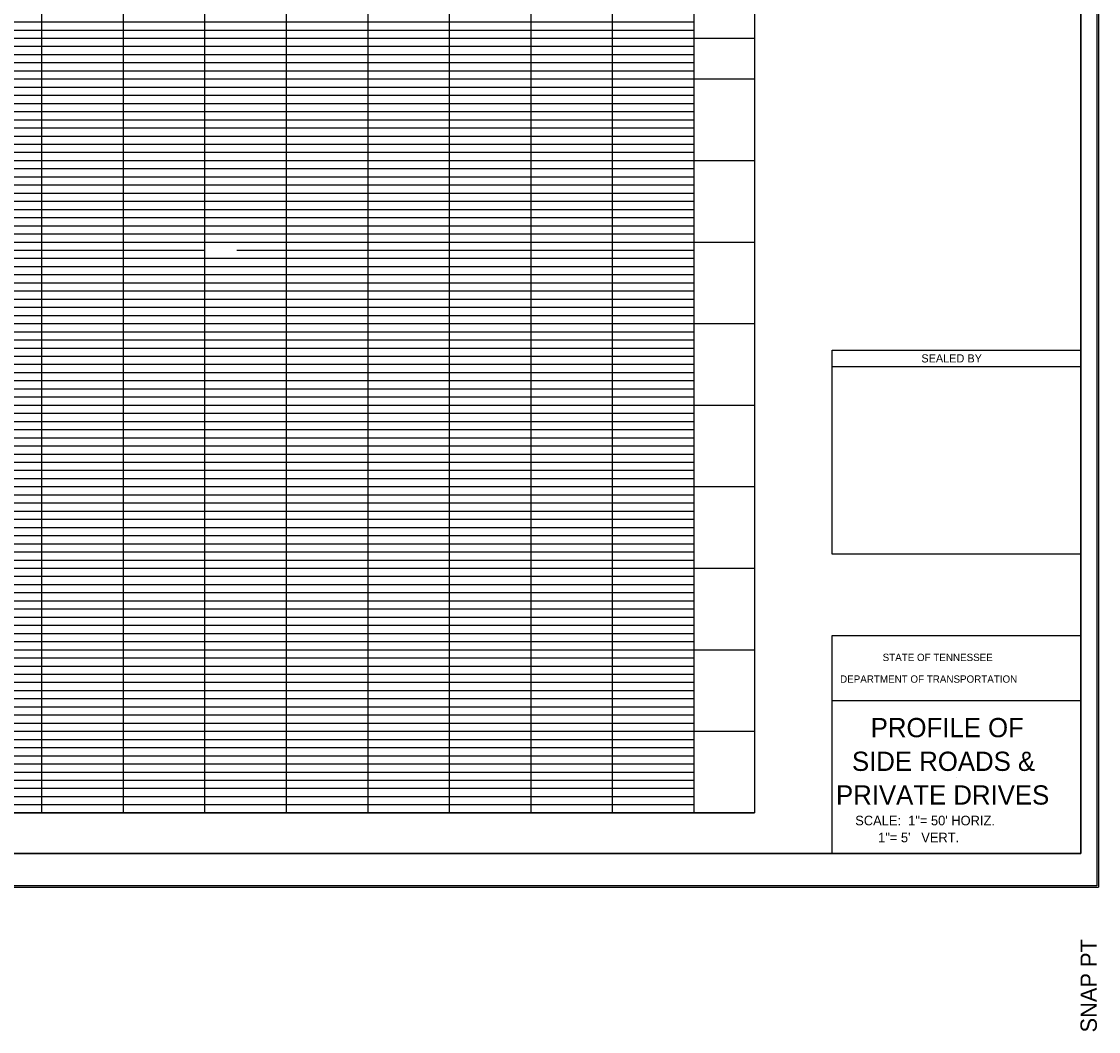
# Model space of a CAD drawing. Extents: x -200 to 1681865, y -325 to 520634.
# Drawn here: x 1681205 to 1681865, y 519391 to 520010 of the extents above; entities that cross this region are included whole.
import ezdxf

# ---------------------------------------------------------------- set-up
doc = ezdxf.new("R2010")
doc.units = 0
for name, color, linetype in [('DESIGN - SCRATCH - User 1', 7, 'Continuous'), ('DESIGN - SHEET - Corner Text', 7, 'Continuous'), ('DESIGN - SHEET - Light Grid', 7, 'Continuous'), ('DESIGN - SHEET - Linework', 7, 'Continuous'), ('DESIGN - SHEET - Plot Shape', 7, 'Continuous')]:
    doc.layers.add(name, color=color, linetype=linetype)

msp = doc.modelspace()

# ---------------------------------------------------------------- linework, layer by layer
at = {"layer": 'DESIGN - SCRATCH - User 1'}
msp.add_line((1681777.98, 519546.56), (1681777.98, 519546.56), dxfattribs=at)
at = {"layer": 'DESIGN - SHEET - Corner Text'}
msp.add_line((1680280.03, 519999.76), (1681654.23, 519999.76), dxfattribs=at)
at = {"layer": 'DESIGN - SHEET - Light Grid'}
for p, q in [((1680967.13, 520009.76), (1681317.13, 520009.76)), ((1681317.13, 520009.76), (1681617.13, 520009.76)), ((1680967.13, 520004.76), (1681317.13, 520004.76)), ((1680967.13, 519999.76), (1681317.13, 519999.76)), ((1681317.13, 520004.76), (1681617.13, 520004.76)), ((1681317.13, 519999.76), (1681617.13, 519999.76)), ((1680967.13, 519994.76), (1681317.13, 519994.76)), ((1681317.13, 519994.76), (1681617.13, 519994.76)), ((1680967.13, 519989.76), (1681317.13, 519989.76)), ((1681317.13, 519989.76), (1681617.13, 519989.76)), ((1680967.13, 519984.76), (1681317.13, 519984.76)), ((1680967.13, 519979.76), (1681317.13, 519979.76)), ((1681317.13, 519984.76), (1681617.13, 519984.76)), ((1681317.13, 519979.76), (1681617.13, 519979.76)), ((1680967.13, 519969.76), (1681317.13, 519969.76)), ((1681317.13, 519969.76), (1681617.13, 519969.76)), ((1680967.13, 519964.76), (1681317.13, 519964.76)), ((1680967.13, 519959.76), (1681317.13, 519959.76)), ((1681317.13, 519964.76), (1681617.13, 519964.76)), ((1681317.13, 519959.76), (1681617.13, 519959.76)), ((1680967.13, 519954.76), (1681317.13, 519954.76)), ((1681317.13, 519954.76), (1681617.13, 519954.76)), ((1680967.13, 519949.76), (1681317.13, 519949.76)), ((1681317.13, 519949.76), (1681617.13, 519949.76)), ((1680967.13, 519944.76), (1681317.13, 519944.76)), ((1680967.13, 519939.76), (1681317.13, 519939.76)), ((1681317.13, 519944.76), (1681617.13, 519944.76)), ((1681317.13, 519939.76), (1681617.13, 519939.76)), ((1680967.13, 519934.76), (1681317.13, 519934.76)), ((1681317.13, 519934.76), (1681617.13, 519934.76)), ((1680967.13, 519929.76), (1681317.13, 519929.76)), ((1681317.13, 519929.76), (1681617.13, 519929.76)), ((1680967.13, 519919.76), (1681317.13, 519919.76)), ((1681317.13, 519919.76), (1681617.13, 519919.76)), ((1680967.13, 519914.76), (1681317.13, 519914.76)), ((1681317.13, 519914.76), (1681617.13, 519914.76)), ((1680967.13, 519909.76), (1681317.13, 519909.76)), ((1681317.13, 519909.76), (1681617.13, 519909.76)), ((1680967.13, 519904.76), (1681317.13, 519904.76)), ((1680967.13, 519899.76), (1681317.13, 519899.76)), ((1681317.13, 519904.76), (1681617.13, 519904.76)), ((1681317.13, 519899.76), (1681617.13, 519899.76)), ((1680967.13, 519894.76), (1681317.13, 519894.76)), ((1681317.13, 519894.76), (1681617.13, 519894.76)), ((1680967.13, 519889.76), (1681317.13, 519889.76)), ((1681317.13, 519889.76), (1681617.13, 519889.76)), ((1680967.13, 519884.76), (1681317.13, 519884.76)), ((1681317.13, 519884.76), (1681617.13, 519884.76)), ((1680967.13, 519879.76), (1681317.13, 519879.76)), ((1681317.13, 519879.76), (1681617.13, 519879.76)), ((1680967.13, 519869.76), (1681317.13, 519869.76)), ((1681336.76, 519869.76), (1681617.13, 519869.76)), ((1680967.13, 519864.76), (1681317.13, 519864.76)), ((1681317.13, 519864.76), (1681617.13, 519864.76)), ((1680967.13, 519859.76), (1681317.13, 519859.76)), ((1680967.13, 519854.76), (1681317.13, 519854.76)), ((1681317.13, 519859.76), (1681617.13, 519859.76)), ((1681317.13, 519854.76), (1681617.13, 519854.76)), ((1680967.13, 519849.76), (1681317.13, 519849.76)), ((1681317.13, 519849.76), (1681617.13, 519849.76)), ((1680967.13, 519844.76), (1681317.13, 519844.76)), ((1681317.13, 519844.76), (1681617.13, 519844.76)), ((1680967.13, 519839.76), (1681317.13, 519839.76)), ((1680967.13, 519834.76), (1681317.13, 519834.76)), ((1681317.13, 519839.76), (1681617.13, 519839.76)), ((1681317.13, 519834.76), (1681617.13, 519834.76)), ((1680967.13, 519829.76), (1681317.13, 519829.76)), ((1681317.13, 519829.76), (1681617.13, 519829.76)), ((1680967.13, 519819.76), (1681317.13, 519819.76)), ((1680967.13, 519814.76), (1681317.13, 519814.76)), ((1681317.13, 519819.76), (1681617.13, 519819.76)), ((1681317.13, 519814.76), (1681617.13, 519814.76)), ((1680967.13, 519809.76), (1681317.13, 519809.76)), ((1681317.13, 519809.76), (1681617.13, 519809.76)), ((1680967.13, 519804.76), (1681317.13, 519804.76)), ((1681317.13, 519804.76), (1681617.13, 519804.76)), ((1680967.13, 519799.76), (1681317.13, 519799.76)), ((1680967.13, 519794.76), (1681317.13, 519794.76)), ((1681317.13, 519799.76), (1681617.13, 519799.76)), ((1681317.13, 519794.76), (1681617.13, 519794.76)), ((1680967.13, 519789.76), (1681317.13, 519789.76)), ((1681317.13, 519789.76), (1681617.13, 519789.76)), ((1680967.13, 519784.76), (1681317.13, 519784.76)), ((1681317.13, 519784.76), (1681617.13, 519784.76)), ((1680967.13, 519779.76), (1681317.13, 519779.76)), ((1681317.13, 519779.76), (1681617.13, 519779.76)), ((1680967.13, 519769.76), (1681317.13, 519769.76)), ((1681317.13, 519769.76), (1681617.13, 519769.76)), ((1680967.13, 519764.76), (1681317.13, 519764.76)), ((1681317.13, 519764.76), (1681617.13, 519764.76)), ((1680967.13, 519759.76), (1681317.13, 519759.76)), ((1680967.13, 519754.76), (1681317.13, 519754.76)), ((1681317.13, 519759.76), (1681617.13, 519759.76)), ((1681317.13, 519754.76), (1681617.13, 519754.76)), ((1680967.13, 519749.76), (1681317.13, 519749.76)), ((1681317.13, 519749.76), (1681617.13, 519749.76)), ((1680967.13, 519744.76), (1681317.13, 519744.76)), ((1681317.13, 519744.76), (1681617.13, 519744.76)), ((1680967.13, 519739.76), (1681317.13, 519739.76)), ((1680967.13, 519734.76), (1681317.13, 519734.76)), ((1681317.13, 519739.76), (1681617.13, 519739.76)), ((1681317.13, 519734.76), (1681617.13, 519734.76)), ((1680967.13, 519729.76), (1681317.13, 519729.76)), ((1681317.13, 519729.76), (1681617.13, 519729.76)), ((1680967.13, 519719.76), (1681317.13, 519719.76)), ((1680967.13, 519714.76), (1681317.13, 519714.76)), ((1681317.13, 519719.76), (1681617.13, 519719.76)), ((1681317.13, 519714.76), (1681617.13, 519714.76)), ((1680967.13, 519709.76), (1681317.13, 519709.76)), ((1681317.13, 519709.76), (1681617.13, 519709.76)), ((1680967.13, 519704.76), (1681317.13, 519704.76)), ((1681317.13, 519704.76), (1681617.13, 519704.76)), ((1680967.13, 519699.76), (1681317.13, 519699.76)), ((1681317.13, 519699.76), (1681617.13, 519699.76)), ((1680967.13, 519694.76), (1681317.13, 519694.76)), ((1680967.13, 519689.76), (1681317.13, 519689.76)), ((1681317.13, 519694.76), (1681617.13, 519694.76)), ((1681317.13, 519689.76), (1681617.13, 519689.76)), ((1680967.13, 519684.76), (1681317.13, 519684.76)), ((1681317.13, 519684.76), (1681617.13, 519684.76)), ((1680967.13, 519679.76), (1681317.13, 519679.76)), ((1681317.13, 519679.76), (1681617.13, 519679.76)), ((1680967.13, 519669.76), (1681317.13, 519669.76)), ((1681317.13, 519669.76), (1681617.13, 519669.76)), ((1680967.13, 519664.76), (1681317.13, 519664.76)), ((1681317.13, 519664.76), (1681617.13, 519664.76)), ((1680967.13, 519659.76), (1681317.13, 519659.76)), ((1681317.13, 519659.76), (1681617.13, 519659.76)), ((1680967.13, 519654.76), (1681317.13, 519654.76)), ((1680967.13, 519649.76), (1681317.13, 519649.76)), ((1681317.13, 519654.76), (1681617.13, 519654.76)), ((1681317.13, 519649.76), (1681617.13, 519649.76)), ((1680967.13, 519644.76), (1681317.13, 519644.76)), ((1681317.13, 519644.76), (1681617.13, 519644.76)), ((1680967.13, 519639.76), (1681317.13, 519639.76)), ((1681317.13, 519639.76), (1681617.13, 519639.76)), ((1680967.13, 519634.76), (1681317.13, 519634.76)), ((1680967.13, 519629.76), (1681317.13, 519629.76)), ((1681317.13, 519634.76), (1681617.13, 519634.76)), ((1681317.13, 519629.76), (1681617.13, 519629.76)), ((1680967.13, 519619.76), (1681317.13, 519619.76)), ((1681317.13, 519619.76), (1681617.13, 519619.76)), ((1680967.13, 519614.76), (1681317.13, 519614.76)), ((1680967.13, 519609.76), (1681317.13, 519609.76)), ((1681317.13, 519614.76), (1681617.13, 519614.76)), ((1681317.13, 519609.76), (1681617.13, 519609.76)), ((1680967.13, 519604.76), (1681317.13, 519604.76)), ((1681317.13, 519604.76), (1681617.13, 519604.76)), ((1680967.13, 519599.76), (1681317.13, 519599.76)), ((1681317.13, 519599.76), (1681617.13, 519599.76)), ((1680967.13, 519594.76), (1681317.13, 519594.76)), ((1680967.13, 519589.76), (1681317.13, 519589.76)), ((1681317.13, 519594.76), (1681617.13, 519594.76)), ((1681317.13, 519589.76), (1681617.13, 519589.76)), ((1680967.13, 519584.76), (1681317.13, 519584.76)), ((1681317.13, 519584.76), (1681617.13, 519584.76)), ((1680967.13, 519579.76), (1681317.13, 519579.76)), ((1681317.13, 519579.76), (1681617.13, 519579.76)), ((1680967.13, 519569.76), (1681317.13, 519569.76)), ((1681317.13, 519569.76), (1681617.13, 519569.76)), ((1680967.13, 519564.76), (1681317.13, 519564.76)), ((1681317.13, 519564.76), (1681617.13, 519564.76)), ((1680967.13, 519559.76), (1681317.13, 519559.76)), ((1681317.13, 519559.76), (1681617.13, 519559.76)), ((1680967.13, 519554.76), (1681317.13, 519554.76)), ((1680967.13, 519549.76), (1681317.13, 519549.76)), ((1681317.13, 519554.76), (1681617.13, 519554.76)), ((1681317.13, 519549.76), (1681617.13, 519549.76)), ((1680967.13, 519544.76), (1681317.13, 519544.76)), ((1681317.13, 519544.76), (1681617.13, 519544.76)), ((1680967.13, 519539.76), (1681317.13, 519539.76)), ((1681317.13, 519539.76), (1681617.13, 519539.76)), ((1680967.13, 519534.76), (1681317.13, 519534.76)), ((1681317.13, 519534.76), (1681617.13, 519534.76)), ((1680967.13, 519529.76), (1681317.13, 519529.76)), ((1681317.13, 519529.76), (1681617.13, 519529.76))]:
    msp.add_line(p, q, dxfattribs=at)
at = {"layer": 'DESIGN - SHEET - Linework'}
for p, q in [((1681865.08, 520570.46), (1681865.08, 519479.06)), ((1681217.13, 519524.76), (1681217.13, 520524.76)), ((1681267.13, 519524.76), (1681267.13, 520524.76)), ((1681317.13, 519524.76), (1681317.13, 520524.76)), ((1681367.13, 519524.76), (1681367.13, 520524.76)), ((1681417.13, 519524.76), (1681417.13, 520524.76)), ((1681467.13, 519524.76), (1681467.13, 520524.76)), ((1681517.13, 519524.76), (1681517.13, 520524.76)), ((1681567.13, 519524.76), (1681567.13, 520524.76)), ((1681617.13, 519524.76), (1681617.13, 520524.76)), ((1680280.03, 519974.76), (1681654.23, 519974.76)), ((1680280.03, 519924.76), (1681654.23, 519924.76)), ((1680280.03, 519874.76), (1681654.23, 519874.76)), ((1680280.03, 519824.76), (1681654.23, 519824.76)), ((1681701.73, 519798.41), (1681854.23, 519798.41)), ((1680280.03, 519774.76), (1681654.23, 519774.76)), ((1680280.03, 519724.76), (1681654.23, 519724.76)), ((1680280.03, 519674.76), (1681654.23, 519674.76)), ((1680280.03, 519624.76), (1681654.23, 519624.76)), ((1680280.03, 519574.76), (1681654.23, 519574.76)), ((1680280.03, 519524.76), (1681654.23, 519524.76)), ((1680163.08, 519479.06), (1681865.08, 519479.06))]:
    msp.add_line(p, q, dxfattribs=at)
for points in [[(1680280.03, 520549.76), (1680280.03, 519499.76), (1681854.23, 519499.76), (1681854.23, 520549.76), (1680280.03, 520549.76)], [(1680280.03, 519524.76), (1680280.03, 520524.76), (1681654.23, 520524.76), (1681654.23, 519524.76), (1680282.13, 519524.76)], [(1681701.73, 519499.76), (1681701.73, 519633.41), (1681854.23, 519633.41), (1681854.23, 519593.41), (1681701.73, 519593.41)]]:
    msp.add_lwpolyline(points, dxfattribs=at)
msp.add_lwpolyline([(1681854.23, 519683.41), (1681701.73, 519683.41), (1681701.73, 519808.41), (1681854.23, 519808.41)], close=True, dxfattribs=at)
at = {"layer": 'DESIGN - SHEET - Plot Shape'}
for points in [[(1680164.08, 520569.46), (1681864.08, 520569.46), (1681864.08, 519480.06), (1680164.08, 519480.06)], [(1680194.98, 520549.76), (1681854.23, 520549.76), (1681854.23, 519499.76), (1680194.98, 519499.76)]]:
    msp.add_lwpolyline(points, close=True, dxfattribs=at)

# ---------------------------------------------------------------- texts
at = {"layer": 'DESIGN - SHEET - Corner Text'}
for s, height, rotation, p in [('SEALED BY', 5, 360, (1681756.46, 519800.91)), ('SNAP PT  ', 10, 90, (1681864.08, 519390.06))]:
    msp.add_text(s, height=height, rotation=rotation, dxfattribs=at).set_placement(p)
for s, height, p in [('STATE OF TENNESSEE', 4.5, (1681732.73, 519617.81)), ('DEPARTMENT OF TRANSPORTATION', 4.5, (1681706.63, 519604.51)), ('PROFILE OF', 11.811, (1681725.41, 519571.09)), ('SIDE ROADS &', 11.811, (1681713.91, 519550.43)), ('PRIVATE DRIVES', 11.811, (1681704.14, 519529.77)), ('SCALE:  1"= 50\' HORIZ.', 5.9001, (1681715.93, 519517.06)), ('         1"= 5\'   VERT. ', 5.9001, (1681710.23, 519506.66))]:
    msp.add_text(s, height=height, dxfattribs=at).set_placement(p)

doc.saveas('drawing.dxf')
